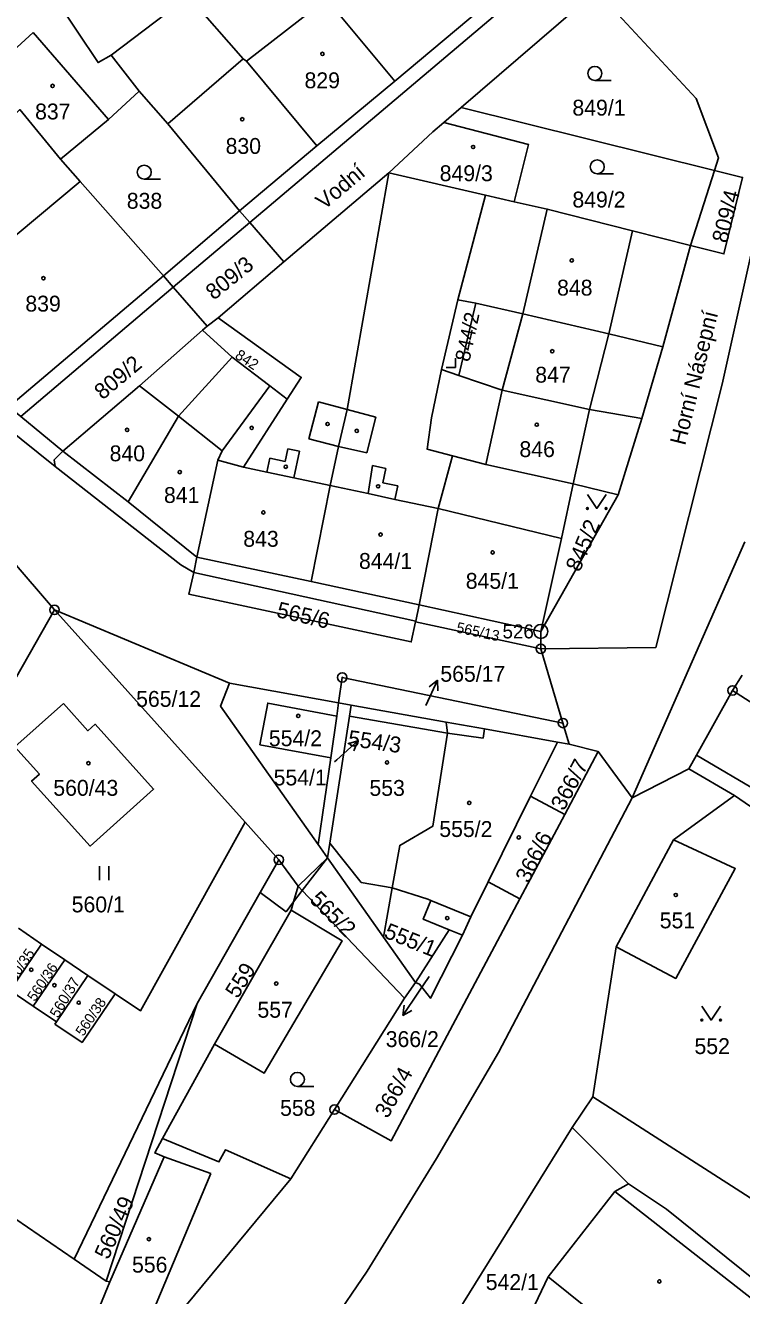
# Model space of a CAD drawing. Extents: x -776606 to -776076, y -974328 to -973875.
# Drawn here: x -776270.5 to -776193.8, y -974133.7 to -973997.7 of the extents above; entities that cross this region are included whole.
import ezdxf

# ---------------------------------------------------------------- set-up
doc = ezdxf.new("R2010")
doc.units = 0
for name, color, linetype in [('Hranice parcel', 7, 'Continuous'), ('Parcelní čísla', 7, 'Continuous'), ('Pop  PČ popisy', 7, 'Continuous'), ('Poz předměty', 7, 'Continuous'), ('Vnitřní kresba', 7, 'Continuous'), ('Značky bodu BP', 7, 'Continuous'), ('Značky budov', 7, 'Continuous'), ('Značky kultur', 7, 'Continuous')]:
    doc.layers.add(name, color=color, linetype=linetype)

msp = doc.modelspace()

# ---------------------------------------------------------------- linework, layer by layer
at = {"layer": 'Hranice parcel'}
for p, q in [((-776254.25, -973995.57), (-776261.3, -974000.9)), ((-776261.3, -974000.9), (-776258.29, -974004.76)), ((-776239.27, -974010.62), (-776230.92, -974003.68)), ((-776225.69, -974008.12), (-776223.84, -974006.53)), ((-776223.84, -974006.53), (-776196.71, -974013.25)), ((-776247.57, -974017.58), (-776239.27, -974010.62)), ((-776231.58, -974013.49), (-776242.81, -974023.05)), ((-776221.22, -974015.91), (-776231.58, -974013.49)), ((-776199.27, -974021.29), (-776196.71, -974013.25)), ((-776224.19, -974027.09), (-776221.22, -974015.91)), ((-776218.16, -974016.6), (-776221.22, -974015.91)), ((-776255.71, -974024.55), (-776247.57, -974017.58)), ((-776202.25, -974032.14), (-776199.27, -974021.29)), ((-776242.81, -974023.05), (-776249.83, -974029.02)), ((-776272.25, -974038.56), (-776255.71, -974024.55)), ((-776225.94, -974034.56), (-776224.19, -974027.09)), ((-776222.25, -974027.45), (-776224.19, -974027.09)), ((-776224.09, -974035.2), (-776222.25, -974027.45)), ((-776249.83, -974029.02), (-776251.01, -974029.93)), ((-776251.01, -974029.93), (-776251.54, -974030.34)), ((-776248.36, -974033.23), (-776251.54, -974030.34)), ((-776204.48, -974039.81), (-776202.25, -974032.14)), ((-776244.32, -974036.32), (-776248.36, -974033.23)), ((-776225.94, -974034.56), (-776224.09, -974035.2)), ((-776207.02, -974047.99), (-776204.48, -974039.81)), ((-776266.49, -974043.3), (-776259.49, -974048.74)), ((-776207.02, -974047.99), (-776211.83, -974046.79)), ((-776215.3, -974062.6), (-776207.02, -974047.99)), ((-776259.49, -974048.74), (-776252.12, -974054.65)), ((-776252.12, -974054.65), (-776252.47, -974056.28)), ((-776252.12, -974054.65), (-776239.9, -974057.27)), ((-776239.9, -974057.27), (-776228.31, -974059.76)), ((-776267.37, -974060.3), (-776282.47, -974086.79)), ((-776248.62, -974068.16), (-776267.37, -974060.3)), ((-776246.97, -974083.03), (-776267.37, -974060.3)), ((-776228.69, -974061.51), (-776228.31, -974059.76)), ((-776228.31, -974059.76), (-776215.3, -974062.6)), ((-776228.71, -974061.56), (-776228.69, -974061.51)), ((-776228.71, -974061.56), (-776215.3, -974064.46)), ((-776215.3, -974064.46), (-776215.3, -974062.6)), ((-776215.3, -974064.46), (-776212.94, -974072.41)), ((-776194.77, -974068.92), (-776193.76, -974067.27)), ((-776236.95, -974070.25), (-776248.62, -974068.16)), ((-776198.63, -974075.84), (-776194.77, -974068.92)), ((-776194.77, -974068.92), (-776186.22, -974074.45)), ((-776237.15, -974071.66), (-776236.95, -974070.25)), ((-776235.6, -974070.5), (-776236.95, -974070.25)), ((-776237.8, -974076.14), (-776237.15, -974071.66)), ((-776225.44, -974072.32), (-776235.6, -974070.5)), ((-776221.34, -974073.05), (-776225.44, -974072.32)), ((-776213.53, -974074.46), (-776221.34, -974073.05)), ((-776212.94, -974072.41), (-776212.26, -974074.69)), ((-776216.39, -974080.23), (-776213.53, -974074.46)), ((-776213.53, -974074.46), (-776212.26, -974074.69)), ((-776239.15, -974085.41), (-776237.8, -974076.14)), ((-776220.94, -974089.42), (-776216.39, -974080.23)), ((-776212.74, -974082.19), (-776216.39, -974080.23)), ((-776201.1, -974084.92), (-776194.55, -974080.16)), ((-776212.74, -974082.19), (-776217.54, -974091.22)), ((-776243.36, -974087.05), (-776246.97, -974083.03)), ((-776207.22, -974096.36), (-776201.1, -974084.92)), ((-776239.15, -974085.41), (-776238.14, -974086.83)), ((-776241.29, -974089.86), (-776243.36, -974087.05)), ((-776238.14, -974086.83), (-776240.84, -974090.34)), ((-776238.14, -974086.83), (-776232.15, -974095.34)), ((-776240.84, -974090.34), (-776241.29, -974089.86)), ((-776229.91, -974101.87), (-776240.84, -974090.34)), ((-776232.15, -974095.34), (-776231.21, -974090.06)), ((-776227.41, -974091.26), (-776231.21, -974090.06)), ((-776217.54, -974091.22), (-776220.94, -974089.42)), ((-776242.03, -974092.45), (-776250.25, -974106.78)), ((-776271.24, -974094.39), (-776268.76, -974096.07)), ((-776225.1, -974094.56), (-776228.73, -974100.18)), ((-776223.7, -974095.13), (-776225.1, -974094.56)), ((-776272.12, -974101.04), (-776268.76, -974096.07)), ((-776268.76, -974096.07), (-776266.27, -974097.75)), ((-776232.15, -974095.34), (-776228.73, -974100.18)), ((-776209.73, -974112.42), (-776207.22, -974096.36)), ((-776269.64, -974102.72), (-776266.27, -974097.75)), ((-776266.27, -974097.75), (-776263.79, -974099.43)), ((-776267.15, -974104.4), (-776263.79, -974099.43)), ((-776263.79, -974099.43), (-776260.89, -974101.39)), ((-776228.73, -974100.18), (-776229.91, -974101.87)), ((-776228.73, -974100.18), (-776228.3, -974100.37)), ((-776269.64, -974102.72), (-776272.12, -974101.04)), ((-776267.15, -974104.4), (-776269.64, -974102.72)), ((-776265.27, -974129.8), (-776252.11, -974102.44)), ((-776252.11, -974102.44), (-776261.84, -974132.15)), ((-776229.91, -974101.87), (-776237.39, -974113.79)), ((-776267.32, -974104.65), (-776267.15, -974104.4)), ((-776250.25, -974106.78), (-776255.8, -974116.9)), ((-776211.93, -974115.7), (-776209.73, -974112.42)), ((-776191.49, -974124.12), (-776209.73, -974112.42)), ((-776237.39, -974113.79), (-776242.05, -974121.22)), ((-776229.3, -974143.65), (-776211.93, -974115.7)), ((-776192.75, -974134.02), (-776207.36, -974122.58)), ((-776261.84, -974132.15), (-776265.27, -974129.8)), ((-776261.84, -974132.15), (-776261.46, -974132.25))]:
    msp.add_line(p, q, dxfattribs=at)
for points in [[(-776348.8, -973929.48), (-776343.01, -973940.47), (-776336.28, -973951.4), (-776326.2, -973966.93), (-776309.58, -973992.58), (-776304.42, -974001.08), (-776303.62, -974003.12), (-776297.56, -974011.17), (-776288.84, -974021.6), (-776272.77, -974040.55), (-776267.29, -974044.95), (-776253.84, -974055.49), (-776252.47, -974056.28)], [(-776230.92, -974003.68), (-776213.75, -973989.29), (-776241.31, -973958.73)], [(-776243.98, -973988.1), (-776238.25, -973994.88), (-776230.92, -974003.68)], [(-776196.71, -974013.25), (-776196.28, -974011.91), (-776198.67, -974005.55), (-776209.34, -973994.03), (-776223.84, -974006.53)], [(-776267.2, -973994.95), (-776262.7, -974001.7), (-776261.3, -974000.9)], [(-776253.07, -973994.57), (-776247.18, -974001.31), (-776246.82, -974001.54), (-776239.27, -974010.62)], [(-776186.87, -973995.48), (-776195.9, -974036.12), (-776202.98, -974064.31), (-776215.3, -974064.46)], [(-776266.72, -974012.05), (-776261.58, -974007.81), (-776258.29, -974004.76)], [(-776258.29, -974004.76), (-776255.23, -974008.26), (-776247.57, -974017.58)], [(-776274.81, -974010.35), (-776271.09, -974006.74), (-776266.72, -974012.05)], [(-776231.58, -974013.49), (-776226.86, -974009.13), (-776225.69, -974008.12)], [(-776225.69, -974008.12), (-776216.63, -974010.46), (-776218.16, -974016.6)], [(-776267.37, -974060.3), (-776281.86, -974043.45), (-776308.52, -974010.36)], [(-776266.72, -974012.05), (-776264.63, -974014.42), (-776255.71, -974024.55)], [(-776239.9, -974057.27), (-776237.86, -974046.99), (-776236.96, -974042.81), (-776236.02, -974038.84), (-776231.58, -974013.49)], [(-776196.71, -974013.25), (-776193.7, -974014), (-776195.7, -974022.19), (-776199.27, -974021.29)], [(-776199.27, -974021.29), (-776205.48, -974019.71), (-776214.61, -974017.38), (-776218.16, -974016.6)], [(-776247.57, -974017.58), (-776246.47, -974018.84), (-776242.81, -974023.05)], [(-776251.01, -974029.93), (-776254.65, -974025.76), (-776255.71, -974024.55)], [(-776202.25, -974032.14), (-776208.03, -974030.74), (-776217.23, -974028.62), (-776222.25, -974027.45)], [(-776244.32, -974036.32), (-776242.45, -974037.75), (-776240.95, -974035.41), (-776249.83, -974029.02)], [(-776251.54, -974030.34), (-776258.26, -974036.31), (-776266.49, -974043.3)], [(-776259.49, -974048.74), (-776254.11, -974039.57), (-776248.36, -974033.23)], [(-776224.75, -974043.8), (-776227.47, -974043.1), (-776227, -974039.72), (-776225.94, -974034.56)], [(-776252.12, -974054.65), (-776249.88, -974044.26), (-776249.42, -974043.26), (-776244.32, -974036.32)], [(-776204.48, -974039.81), (-776210.09, -974038.84), (-776219.45, -974036.78), (-776224.09, -974035.2)], [(-776266.49, -974043.3), (-776270.99, -974039.59), (-776272.25, -974038.56)], [(-776228.31, -974059.76), (-776226.31, -974049.45), (-776224.75, -974043.8)], [(-776211.83, -974046.79), (-776221.19, -974044.73), (-776224.75, -974043.8)], [(-776215.3, -974062.6), (-776213.1, -974052.64), (-776211.83, -974046.79)], [(-776252.47, -974056.28), (-776252.98, -974058.63), (-776229.18, -974063.72), (-776228.71, -974061.56)], [(-776212.94, -974072.41), (-776236.56, -974067.53), (-776236.95, -974070.25)], [(-776248.62, -974068.16), (-776249.58, -974070.59), (-776239.15, -974085.41)], [(-776266.42, -974070.32), (-776263.79, -974073.24), (-776263.01, -974072.55), (-776256.77, -974079.49), (-776263.55, -974085.59), (-776269.82, -974078.62), (-776268.99, -974077.88), (-776271.61, -974074.97), (-776266.42, -974070.32)], [(-776237.8, -974076.14), (-776245.37, -974074.74), (-776244.54, -974070.27), (-776237.15, -974071.66)], [(-776235.6, -974070.5), (-776235.78, -974071.68), (-776237.9, -974085.29), (-776238.14, -974086.83)], [(-776231.21, -974090.06), (-776230.4, -974085.52), (-776226.87, -974083.47), (-776225.3, -974073.49), (-776225.44, -974072.32)], [(-776212.26, -974074.69), (-776209.16, -974075.46), (-776212.74, -974082.19)], [(-776194.55, -974080.16), (-776199.45, -974077.31), (-776198.63, -974075.84)], [(-776198.63, -974075.84), (-776191.6, -974079.99), (-776185.25, -974085.51), (-776183.37, -974096.97), (-776188.41, -974115.88), (-776187.78, -974126.09)], [(-776191.49, -974124.12), (-776186.99, -974097.43), (-776190.67, -974082.84), (-776194.55, -974080.16)], [(-776260.89, -974101.39), (-776258.17, -974103.23), (-776246.97, -974083.03)], [(-776207.22, -974096.36), (-776200.86, -974099.76), (-776194.48, -974087.99), (-776201.1, -974084.92)], [(-776243.36, -974087.05), (-776245.36, -974090.57), (-776252.11, -974102.44)], [(-776241.29, -974089.86), (-776241.78, -974091.56), (-776242.03, -974092.45)], [(-776220.94, -974089.42), (-776222.79, -974093.16), (-776223.7, -974095.13)], [(-776321.52, -974091.59), (-776295.28, -974109.27), (-776265.27, -974129.8)], [(-776217.54, -974091.22), (-776231.34, -974117.15), (-776237.39, -974113.79)], [(-776225.1, -974094.56), (-776227.89, -974093.42), (-776227.06, -974091.41), (-776227.41, -974091.26)], [(-776250.25, -974106.78), (-776244.91, -974109.88), (-776236.57, -974095.73), (-776242.03, -974092.45)], [(-776228.3, -974100.37), (-776227.13, -974101.88), (-776223.7, -974095.13)], [(-776260.89, -974101.39), (-776264.42, -974106.61), (-776267.32, -974104.65)], [(-776211.93, -974115.7), (-776205.92, -974121.75), (-776207.36, -974122.58)], [(-776255.8, -974116.9), (-776256.64, -974118.44), (-776255.64, -974118.87), (-776261.46, -974132.25)], [(-776242.05, -974121.22), (-776249.07, -974118.09), (-776249.76, -974119.4), (-776255.8, -974116.9)], [(-776242.05, -974121.22), (-776258.05, -974140.53), (-776267.35, -974155.99), (-776274.82, -974171.4)], [(-776207.36, -974122.58), (-776214.5, -974131.7), (-776217.69, -974138.39)], [(-776261.46, -974132.25), (-776263.57, -974137.45), (-776267.68, -974145.84), (-776274.82, -974171.4)]]:
    msp.add_lwpolyline(points, dxfattribs=at)
at = {"layer": 'Pop  PČ popisy'}
for p, q in [((-776227.63, -974070.55), (-776226.36, -974067.83)), ((-776226.36, -974067.83), (-776227.24, -974068.53)), ((-776226.36, -974067.83), (-776226.33, -974068.95)), ((-776237.13, -974076.34), (-776234.9, -974074.33)), ((-776234.9, -974074.33), (-776235.98, -974074.63)), ((-776234.9, -974074.33), (-776235.31, -974075.37)), ((-776237.39, -974076.57), (-776237.13, -974076.34)), ((-776227.25, -974099.53), (-776228.41, -974101.24)), ((-776228.41, -974101.24), (-776230.09, -974103.73)), ((-776230.09, -974103.73), (-776229.94, -974102.62)), ((-776230.09, -974103.73), (-776229.11, -974103.18))]:
    msp.add_line(p, q, dxfattribs=at)
at = {"layer": 'Poz předměty'}
for p, q in [((-776193.46, -974053.03), (-776205.51, -974080.41)), ((-776205.51, -974080.41), (-776219.84, -974107.68)), ((-776219.84, -974107.68), (-776226.48, -974119.04)), ((-776226.48, -974119.04), (-776233.9, -974131.08)), ((-776233.9, -974131.08), (-776247.26, -974150.66))]:
    msp.add_line(p, q, dxfattribs=at)
at = {"layer": 'Vnitřní kresba'}
for p, q in [((-776246.47, -974018.84), (-776212.73, -973990.29)), ((-776246.82, -974001.54), (-776238.25, -973994.88)), ((-776274.36, -974002.77), (-776269.67, -973998.49)), ((-776269.67, -973998.49), (-776261.58, -974007.81)), ((-776255.23, -974008.26), (-776247.18, -974001.31)), ((-776264.63, -974014.42), (-776280.99, -974028.12)), ((-776214.61, -974017.38), (-776217.23, -974028.62)), ((-776254.65, -974025.76), (-776246.47, -974018.84)), ((-776208.03, -974030.74), (-776205.48, -974019.71)), ((-776270.99, -974039.59), (-776254.65, -974025.76)), ((-776217.23, -974028.62), (-776219.45, -974036.78)), ((-776210.09, -974038.84), (-776208.03, -974030.74)), ((-776254.11, -974039.57), (-776258.26, -974036.31)), ((-776219.45, -974036.78), (-776221.19, -974044.73)), ((-776242.45, -974037.75), (-776247.13, -974045.01)), ((-776240.13, -974042), (-776239.09, -974038.04)), ((-776239.09, -974038.04), (-776236.02, -974038.84)), ((-776236.02, -974038.84), (-776232.95, -974039.65)), ((-776211.83, -974046.79), (-776210.09, -974038.84)), ((-776249.42, -974043.26), (-776254.11, -974039.57)), ((-776232.95, -974039.65), (-776233.93, -974043.5)), ((-776242.68, -974044.41), (-776242.38, -974043.05)), ((-776242.38, -974043.05), (-776241.14, -974043.31)), ((-776236.96, -974042.81), (-776240.13, -974042)), ((-776233.93, -974043.5), (-776236.96, -974042.81)), ((-776267.39, -974044.25), (-776266.49, -974043.3)), ((-776267.29, -974044.95), (-776267.39, -974044.25)), ((-776249.88, -974044.26), (-776247.13, -974045.01)), ((-776244.63, -974045.54), (-776244.31, -974044.06)), ((-776244.31, -974044.06), (-776242.68, -974044.41)), ((-776241.14, -974043.31), (-776241.74, -974046.16)), ((-776247.13, -974045.01), (-776244.63, -974045.54)), ((-776241.74, -974046.16), (-776244.63, -974045.54)), ((-776233.79, -974047.85), (-776233.31, -974044.85)), ((-776233.31, -974044.85), (-776231.9, -974045.15)), ((-776231.9, -974045.15), (-776232.22, -974046.68)), ((-776241.74, -974046.16), (-776237.86, -974046.99)), ((-776237.86, -974046.99), (-776233.79, -974047.85)), ((-776232.22, -974046.68), (-776230.62, -974047.03)), ((-776230.62, -974047.03), (-776230.92, -974048.47)), ((-776230.92, -974048.47), (-776233.79, -974047.85)), ((-776230.92, -974048.47), (-776226.31, -974049.45)), ((-776226.31, -974049.45), (-776213.1, -974052.64)), ((-776228.69, -974061.51), (-776252.47, -974056.28)), ((-776235.78, -974071.68), (-776225.3, -974073.49)), ((-776221.34, -974073.05), (-776221.49, -974074.04)), ((-776221.49, -974074.04), (-776225.3, -974073.49)), ((-776205.51, -974080.41), (-776209.16, -974075.46)), ((-776199.45, -974077.31), (-776205.51, -974080.41)), ((-776234.55, -974089.5), (-776237.9, -974085.29)), ((-776241.29, -974089.86), (-776238.14, -974086.83)), ((-776242.58, -974092.61), (-776245.36, -974090.57)), ((-776240.84, -974090.34), (-776241.78, -974091.56)), ((-776231.21, -974090.06), (-776234.55, -974089.5)), ((-776241.78, -974091.56), (-776242.58, -974092.61)), ((-776227.06, -974091.41), (-776222.79, -974093.16)), ((-776255.64, -974118.87), (-776250.63, -974120.65)), ((-776250.63, -974120.65), (-776258.47, -974139.33)), ((-776205.92, -974121.75), (-776201.86, -974124.47)), ((-776201.86, -974124.47), (-776164.7, -974154.27)), ((-776214.5, -974131.7), (-776208.12, -974136.82))]:
    msp.add_line(p, q, dxfattribs=at)
at = {"layer": 'Značky bodu BP'}
for centre, radius in [((-776267.37, -974060.3), 0.5), ((-776267.37, -974060.3), 0.0303), ((-776215.3, -974062.6), 0.75), ((-776215.3, -974062.6), 0.03), ((-776215.3, -974064.46), 0.5), ((-776215.3, -974064.46), 0.0303), ((-776236.56, -974067.53), 0.5), ((-776236.56, -974067.53), 0.0303), ((-776194.77, -974068.92), 0.5), ((-776194.77, -974068.92), 0.0303), ((-776212.94, -974072.41), 0.5), ((-776212.94, -974072.41), 0.0303), ((-776243.36, -974087.05), 0.5), ((-776243.36, -974087.05), 0.0303), ((-776237.39, -974113.79), 0.5), ((-776237.39, -974113.79), 0.0303)]:
    msp.add_circle(centre, radius, dxfattribs=at)
at = {"layer": 'Značky budov'}
for centre in [(-776238.69, -974000.77), (-776267.57, -974004.2), (-776247.27, -974007.77), (-776222.55, -974010.74), (-776211.99, -974022.88), (-776268.56, -974024.79), (-776214.08, -974032.61), (-776238.13, -974040.4), (-776215.74, -974040.47), (-776259.6, -974041.03), (-776246.26, -974040.82), (-776235.01, -974041.13), (-776253.96, -974045.54), (-776242.61, -974044.98), (-776232.72, -974047.07), (-776245.01, -974049.86), (-776232.46, -974052.23), (-776220.46, -974054.15), (-776241.28, -974071.65), (-776263.74, -974076.71), (-776231.77, -974076.63), (-776222.96, -974080.96), (-776217.67, -974084.66), (-776200.86, -974090.82), (-776225.32, -974093.3), (-776269.86, -974098.83), (-776243.63, -974100.31), (-776267.38, -974100.49), (-776264.78, -974102.35), (-776257.26, -974127.67), (-776202.61, -974132.19)]:
    msp.add_circle(centre, 0.175, dxfattribs=at)
at = {"layer": 'Značky kultur'}
for p, q in [((-776209.52, -974003.61), (-776207.77, -974003.61)), ((-776257.76, -974014.19), (-776256.01, -974014.19)), ((-776209.26, -974013.61), (-776207.51, -974013.61)), ((-776224.44, -974034.34), (-776224.44, -974033.34)), ((-776225.44, -974034.34), (-776224.44, -974034.34)), ((-776262.56, -974089.25), (-776262.56, -974087.75)), ((-776261.56, -974089.25), (-776261.56, -974087.75)), ((-776241.37, -974111.31), (-776239.62, -974111.31))]:
    msp.add_line(p, q, dxfattribs=at)
for points in [[(-776210.32, -974047.94), (-776209.32, -974049.44), (-776208.32, -974047.94)], [(-776198.07, -974102.71), (-776197.07, -974104.21), (-776196.07, -974102.71)]]:
    msp.add_lwpolyline(points, dxfattribs=at)
for centre, radius in [((-776209.52, -974002.86), 0.75), ((-776257.76, -974013.44), 0.75), ((-776209.26, -974012.86), 0.75), ((-776210.32, -974049.44), 0.1), ((-776208.32, -974049.44), 0.1), ((-776198.07, -974104.21), 0.1), ((-776196.07, -974104.21), 0.1), ((-776241.37, -974110.56), 0.75)]:
    msp.add_circle(centre, radius, dxfattribs=at)

# ---------------------------------------------------------------- texts
at = {"layer": 'Parcelní čísla'}
for s, p in [('829', (-776240.6, -974004.45)), ('837', (-776269.45, -974007.79)), ('849/1', (-776211.92, -974007.38)), ('830', (-776249.05, -974011.48)), ('849/3', (-776226.13, -974014.4)), ('838', (-776259.63, -974017.35)), ('849/2', (-776211.92, -974017.22)), ('848', (-776213.56, -974026.65)), ('839', (-776270.49, -974028.36)), ('847', (-776215.9, -974035.97)), ('840', (-776261.47, -974044.39)), ('846', (-776217.59, -974043.94)), ('841', (-776255.65, -974048.85)), ('843', (-776247.16, -974053.54)), ('844/1', (-776234.77, -974055.91)), ('845/1', (-776223.34, -974058.04)), ('565/17', (-776226.06, -974067.99)), ('565/12', (-776258.63, -974070.68)), ('554/2', (-776244.42, -974074.89)), ('560/43', (-776267.5, -974080.2)), ('554/1', (-776243.91, -974079.09)), ('553', (-776233.65, -974080.21)), ('555/2', (-776226.17, -974084.61)), ('560/1', (-776265.53, -974092.68)), ('551', (-776202.57, -974094.39)), ('557', (-776245.64, -974103.96)), ('366/2', (-776231.91, -974107.1)), ('552', (-776198.85, -974107.85)), ('558', (-776243.22, -974114.47)), ('556', (-776259.07, -974131.25)), ('542/1', (-776221.2, -974133.11))]:
    msp.add_text(s, height=1.7, dxfattribs=at).set_placement(p)
for s, height, rotation, p in [('809/4', 1.7, 76, (-776195.36, -974021.11)), ('809/3', 1.7, 39, (-776250.32, -974027.2)), ('844/2', 1.584, 78, (-776222.95, -974033.81)), ('809/2', 1.7, 40, (-776262.22, -974037.88)), ('842', 1.139, 327, (-776248.13, -974033.29)), ('845/2', 1.7, 67, (-776211.15, -974056.33)), ('565/6', 1.7, 347, (-776243.68, -974061.05)), ('565/13', 1.139, 348, (-776224.42, -974062.7)), ('554/3', 1.7, 352, (-776236.02, -974074.84)), ('366/7', 1.7, 62, (-776212.83, -974081.9)), ('366/6', 1.7, 63, (-776216.6, -974089.65)), ('565/2', 1.7, 315, (-776240.16, -974091.43)), ('555/1', 1.7, 338, (-776232.2, -974095.34)), ('560/35', 1.139, 55, (-776272.09, -974100.89)), ('560/36', 1.1, 56, (-776269.47, -974102.3)), ('559', 1.7, 58, (-776247.76, -974102)), ('560/37', 1.139, 59, (-776266.98, -974104.07)), ('560/38', 1.1, 56, (-776264.29, -974106.02)), ('366/4', 1.7, 61, (-776231.7, -974114.84)), ('560/49', 1.7, 66, (-776261.61, -974129.94))]:
    msp.add_text(s, height=height, rotation=rotation, dxfattribs=at).set_placement(p)
at = {"layer": 'Pop  PČ popisy'}
for s, rotation, p in [('Vodní', 40, (-776238.5, -974017.53)), ('Horní Násepní', 76, (-776199.85, -974042.76))]:
    msp.add_text(s, height=1.7, rotation=rotation, dxfattribs=at).set_placement(p)
at = {"layer": 'Značky bodu BP'}
msp.add_text('526', height=1.5, dxfattribs=at).set_placement((-776219.4, -974063.35))

doc.saveas('drawing.dxf')
